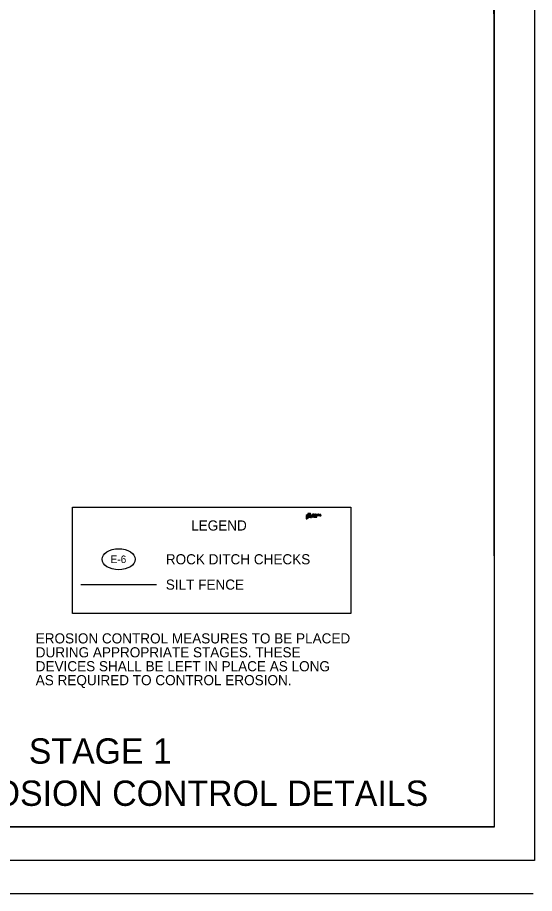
# Model space of a CAD drawing. Extents: x 7675 to 14104, y 9961 to 11168.
# Drawn here: x 11298 to 11605, y 9961 to 10480 of the extents above; entities that cross this region are included whole.
import ezdxf

# ---------------------------------------------------------------- set-up
doc = ezdxf.new("R2010")
doc.units = 0
for name, color, linetype in [('GREEN_TXT', 7, 'Continuous'), ('Legend', 7, 'Continuous'), ('S_TREE', 7, 'Continuous'), ('SEAL-INFO', 7, 'Continuous'), ('Stage 1 Ditch Checks', 7, 'Continuous')]:
    doc.layers.add(name, color=color, linetype=linetype)

msp = doc.modelspace()

# ---------------------------------------------------------------- linework, layer by layer
at = {"layer": 'GREEN_TXT'}
for p, q in [((11580.9, 10000), (11580.9, 11027.3)), ((11580.9, 10000), (10000, 10000)), ((9843.9, 9960.6), (11603.9, 9960.6))]:
    msp.add_line(p, q, dxfattribs=at)
at = {"layer": 'Legend'}
for p, q in [((11469.47, 10183.1), (11470.88, 10183.92)), ((11469.48, 10183.63), (11470.68, 10184.33)), ((11469.48, 10182.58), (11471.09, 10183.5)), ((11470.76, 10185.41), (11471.69, 10185.41)), ((11471.71, 10185.39), (11471.81, 10184.8)), ((11473.03, 10184.29), (11473.03, 10184.3)), ((11473.03, 10183.49), (11473.03, 10183.49)), ((11473.04, 10185.3), (11473.04, 10185.3)), ((11473.04, 10184.49), (11473.04, 10184.49)), ((11473.04, 10183.51), (11473.04, 10183.51)), ((11473.06, 10184.51), (11473.05, 10184.51)), ((11473.05, 10183.46), (11473.23, 10183.46)), ((11473.06, 10184.47), (11473.24, 10184.47)), ((11473.06, 10184.25), (11473.06, 10183.53)), ((11473.07, 10185.26), (11473.07, 10184.54)), ((11473.22, 10183.97), (11473.22, 10184.19)), ((11473.22, 10183.53), (11473.22, 10183.85)), ((11473.23, 10184.92), (11473.23, 10185.21)), ((11473.24, 10184.54), (11473.24, 10184.77)), ((11473.24, 10184.21), (11473.64, 10184.21)), ((11473.52, 10183.95), (11473.24, 10183.95)), ((11473.24, 10183.5), (11473.24, 10183.51)), ((11473.25, 10184.8), (11473.5, 10184.87)), ((11473.25, 10184.51), (11473.25, 10184.51)), ((11473.25, 10183.87), (11473.52, 10183.87)), ((11473.25, 10183.49), (11473.25, 10183.49)), ((11473.26, 10185.24), (11473.34, 10185.24)), ((11473.39, 10184.96), (11473.27, 10184.9)), ((11473.27, 10184.49), (11473.27, 10184.49)), ((11473.56, 10183.84), (11473.56, 10183.83)), ((11473.68, 10184.18), (11473.68, 10184.16)), ((11473.8, 10184.49), (11473.8, 10184.49)), ((11473.81, 10184.01), (11473.82, 10184.01)), ((11473.81, 10183.47), (11474.02, 10183.47)), ((11473.82, 10184.47), (11474.03, 10184.47)), ((11473.97, 10184.05), (11473.82, 10184.05)), ((11473.98, 10185.06), (11473.83, 10185.06)), ((11473.83, 10185.02), (11473.83, 10185.01)), ((11473.83, 10183.99), (11473.83, 10183.53)), ((11473.85, 10184.99), (11473.85, 10184.54)), ((11473.99, 10183.54), (11473.99, 10184.03)), ((11474.01, 10184.54), (11474.01, 10185.04)), ((11474.02, 10183.51), (11474.02, 10183.51)), ((11474.03, 10184.51), (11474.03, 10184.52)), ((11474.19, 10183.46), (11474.4, 10183.46)), ((11474.35, 10184.05), (11474.2, 10184.05)), ((11474.2, 10184.01), (11474.2, 10184.01)), ((11474.21, 10183.99), (11474.21, 10183.53)), ((11474.37, 10183.53), (11474.37, 10183.86)), ((11474.4, 10183.51), (11474.4, 10183.51)), ((11474.57, 10184.9), (11474.64, 10184.98)), ((11474.72, 10184.47), (11474.92, 10184.47)), ((11474.72, 10184.01), (11474.72, 10184.01)), ((11474.87, 10185.32), (11474.73, 10185.32)), ((11474.73, 10185.28), (11474.73, 10185.28)), ((11474.73, 10183.99), (11474.73, 10183.53)), ((11474.74, 10185.26), (11474.74, 10184.53)), ((11474.9, 10184.86), (11474.9, 10185.3)), ((11474.9, 10184.69), (11474.97, 10184.75)), ((11474.9, 10184.53), (11474.9, 10184.67)), ((11474.9, 10183.54), (11474.9, 10183.86)), ((11474.92, 10183.51), (11474.92, 10183.51)), ((11475.08, 10184.97), (11474.94, 10184.84)), ((11475.01, 10184.74), (11475.13, 10184.53)), ((11475.08, 10185.04), (11475.09, 10185)), ((11475.31, 10185.07), (11475.1, 10185.07)), ((11475.1, 10183.51), (11475.1, 10183.51)), ((11475.12, 10184.47), (11475.37, 10184.47)), ((11475.12, 10183.86), (11475.12, 10183.54)), ((11475.14, 10184.9), (11475.29, 10185.03)), ((11475.34, 10184.52), (11475.14, 10184.87)), ((11475.28, 10183.54), (11475.28, 10183.87)), ((11475.31, 10185.03), (11475.32, 10185.03)), ((11475.31, 10183.51), (11475.31, 10183.51)), ((11475.33, 10185.04), (11475.33, 10185.05)), ((11475.51, 10184.9), (11475.51, 10184.9)), ((11475.51, 10183.87), (11475.51, 10183.53)), ((11475.52, 10184.82), (11475.87, 10184.82)), ((11475.72, 10184.87), (11475.53, 10184.87)), ((11475.67, 10183.54), (11475.67, 10183.87)), ((11475.7, 10183.51), (11475.69, 10183.51)), ((11475.87, 10184.62), (11475.87, 10184.62)), ((11475.97, 10184.47), (11476.19, 10184.47)), ((11475.98, 10185.02), (11475.98, 10185.01)), ((11476.14, 10185.06), (11475.99, 10185.06)), ((11476, 10184.99), (11476, 10184.54)), ((11476.16, 10184.54), (11476.16, 10184.87)), ((11476.19, 10184.51), (11476.18, 10184.52)), ((11476.44, 10184.47), (11476.65, 10184.47)), ((11476.45, 10185.02), (11476.45, 10185.01)), ((11476.6, 10185.06), (11476.46, 10185.06)), ((11476.47, 10184.99), (11476.47, 10184.54)), ((11476.63, 10184.54), (11476.63, 10185.03)), ((11476.65, 10184.51), (11476.65, 10184.52)), ((11476.76, 10184.47), (11476.97, 10184.47)), ((11476.77, 10185.02), (11476.77, 10185.01)), ((11476.92, 10185.06), (11476.78, 10185.06)), ((11476.79, 10184.99), (11476.79, 10184.54)), ((11476.95, 10184.54), (11476.95, 10184.87)), ((11476.97, 10184.51), (11476.97, 10184.52)), ((11477.15, 10184.47), (11477.36, 10184.47)), ((11477.17, 10184.87), (11477.17, 10184.54)), ((11477.33, 10184.54), (11477.33, 10184.87)), ((11477.36, 10184.51), (11477.36, 10184.52)), ((11478.03, 10185.06), (11477.8, 10185.06)), ((11477.86, 10184.94), (11477.86, 10184.65)), ((11477.88, 10184.46), (11477.88, 10184.46)), ((11478, 10184.63), (11478, 10184.98)), ((11478.01, 10185), (11478.05, 10185.02)), ((11335.77, 10143.59), (11380.77, 10143.59))]:
    msp.add_line(p, q, dxfattribs=at)
msp.add_lwpolyline([(11330.89, 10189.39), (11495.89, 10189.39), (11495.89, 10126.39), (11330.89, 10126.39)], close=True, dxfattribs=at)
for points in [[(11472.14, 10185.07), (11472.02, 10185.76), (11472, 10185.78), (11470.43, 10185.78), (11470.4, 10185.76), (11470.28, 10185.05), (11469.44, 10184.57), (11469.43, 10184.54), (11469.43, 10184.17), (11469.47, 10184.15)], [(11470.51, 10184.66), (11469.45, 10184.04), (11469.44, 10184.02), (11469.44, 10183.65), (11469.48, 10183.63)], [(11470.71, 10184.26), (11469.45, 10183.52), (11469.44, 10183.5), (11469.44, 10183.12), (11469.47, 10183.1)], [(11470.91, 10183.86), (11469.45, 10182.99), (11469.44, 10182.97), (11469.44, 10182.6), (11469.48, 10182.58)], [(11469.47, 10184.15), (11470.61, 10184.78), (11470.62, 10184.8), (11470.73, 10185.39)], [(11472.53, 10184.59), (11472.55, 10184.61), (11472.55, 10184.93), (11472.53, 10184.96)], [(11472.53, 10184.14), (11472.55, 10184.17), (11472.55, 10184.49), (11472.53, 10184.51)], [(11472.53, 10183.69), (11472.55, 10183.71), (11472.55, 10184.04), (11472.53, 10184.06)], [(11472.53, 10183.23), (11472.55, 10183.25), (11472.55, 10183.59), (11472.53, 10183.62)], [(11473.68, 10184.32), (11473.05, 10184.32), (11473.05, 10184.32)], [(11473.43, 10185.33), (11473.06, 10185.33), (11473.06, 10185.32)], [(11473.57, 10184.01), (11473.58, 10184.01), (11473.57, 10184.01), (11473.56, 10184), (11473.56, 10183.98)], [(11473.57, 10183.82), (11473.58, 10183.82), (11473.57, 10183.82)], [(11473.58, 10183.83), (11473.59, 10183.83), (11473.59, 10184), (11473.58, 10184)], [(11473.7, 10184.16), (11473.71, 10184.16), (11473.71, 10184.3)], [(11473.79, 10183.49), (11473.79, 10183.49), (11473.79, 10183.49)], [(11473.8, 10184.03), (11473.8, 10184.03), (11473.8, 10184.03)], [(11473.81, 10185.04), (11473.81, 10185.04), (11473.81, 10185.04)], [(11473.81, 10183.51), (11473.81, 10183.51), (11473.81, 10183.51)], [(11473.82, 10184.52), (11473.82, 10184.52), (11473.82, 10184.51)], [(11474.04, 10183.49), (11474.04, 10183.49), (11474.04, 10183.49)], [(11474.05, 10184.49), (11474.05, 10184.49), (11474.05, 10184.49)], [(11474.17, 10183.49), (11474.17, 10183.49), (11474.17, 10183.49)], [(11474.18, 10184.03), (11474.18, 10184.03), (11474.18, 10184.03)], [(11474.19, 10183.51), (11474.19, 10183.51), (11474.19, 10183.51)], [(11474.42, 10183.49), (11474.42, 10183.49), (11474.42, 10183.49)], [(11474.55, 10183.98), (11474.59, 10183.95), (11474.6, 10183.96), (11474.6, 10184.08), (11474.59, 10184.1), (11474.54, 10184.1)], [(11474.58, 10184.48), (11474.62, 10184.47), (11474.63, 10184.48), (11474.63, 10184.61)], [(11474.69, 10183.49), (11474.71, 10183.47), (11474.92, 10183.47), (11474.94, 10183.49)], [(11474.89, 10184.04), (11474.87, 10184.05), (11474.72, 10184.05), (11474.7, 10184.03)], [(11474.71, 10183.51), (11474.71, 10183.51), (11474.71, 10183.51)], [(11474.72, 10184.52), (11474.72, 10184.52), (11474.72, 10184.51)], [(11474.92, 10184.51), (11474.92, 10184.52), (11474.92, 10184.52)], [(11475.07, 10183.49), (11475.1, 10183.47), (11475.31, 10183.47), (11475.33, 10183.49)], [(11475.12, 10184.52), (11475.12, 10184.52), (11475.12, 10184.51)], [(11475.37, 10184.51), (11475.37, 10184.52), (11475.36, 10184.52)], [(11475.46, 10183.49), (11475.48, 10183.47), (11475.7, 10183.47), (11475.72, 10183.49)], [(11475.49, 10183.51), (11475.49, 10183.51), (11475.48, 10183.51)], [(11475.84, 10184.48), (11475.88, 10184.47), (11475.89, 10184.48), (11475.89, 10184.61)], [(11475.95, 10184.49), (11475.95, 10184.49), (11475.95, 10184.49)], [(11475.97, 10185.04), (11475.97, 10185.03), (11475.97, 10185.04)], [(11475.98, 10184.52), (11475.98, 10184.52), (11475.97, 10184.51)], [(11476.21, 10184.49), (11476.21, 10184.49), (11476.21, 10184.49)], [(11476.34, 10184.99), (11476.38, 10184.95), (11476.39, 10184.97), (11476.39, 10185.09), (11476.38, 10185.1), (11476.32, 10185.1)], [(11476.42, 10184.49), (11476.42, 10184.49), (11476.42, 10184.49)], [(11476.44, 10185.04), (11476.44, 10185.03), (11476.44, 10185.04)], [(11476.45, 10184.52), (11476.44, 10184.52), (11476.44, 10184.51)], [(11476.68, 10184.49), (11476.68, 10184.49), (11476.68, 10184.49)], [(11476.74, 10184.49), (11476.74, 10184.49), (11476.74, 10184.49)], [(11476.75, 10185.04), (11476.75, 10185.03), (11476.75, 10185.04)], [(11476.77, 10184.52), (11476.76, 10184.52), (11476.76, 10184.51)], [(11476.99, 10184.49), (11476.99, 10184.49), (11476.99, 10184.49)], [(11477.13, 10184.49), (11477.13, 10184.49), (11477.13, 10184.49)], [(11477.15, 10184.52), (11477.15, 10184.52), (11477.15, 10184.51)], [(11477.38, 10184.49), (11477.38, 10184.49), (11477.38, 10184.49)], [(11477.56, 10184.31), (11477.56, 10184.36), (11477.55, 10184.38), (11477.51, 10184.4), (11477.41, 10184.32)]]:
    msp.add_lwpolyline(points, dxfattribs=at)
for centre, radius, start, end in [((11471.23, 10183.21), 1.62, 63.44, 116.2443), ((11471.23, 10183.21), 1.24, 63.4399, 116.2445), ((11471.23, 10183.21), 1.16, 63.4396, 116.2455), ((11470.76, 10185.39), 0.0257, 90, 169.3947), ((11471.23, 10183.21), 0.79, 63.4406, 116.2427), ((11471.23, 10183.21), 0.717, 63.443, 116.2359), ((11471.23, 10183.21), 0.326, 63.4385, 116.2484), ((11472.55, 10185.86), 2.63, 243.4196, 269.4358), ((11472.55, 10185.86), 2.24, 243.4196, 269.3512), ((11472.55, 10185.86), 2.17, 243.4196, 269.3138), ((11471.69, 10185.39), 0.0257, 9.4561, 90), ((11472.55, 10185.86), 1.79, 243.4196, 269.1919), ((11472.55, 10185.86), 1.72, 243.4196, 269.1297), ((11471.23, 10183.21), 1.69, 63.4196, 69.8726), ((11472.55, 10185.86), 1.34, 243.4196, 268.9264), ((11472.55, 10185.86), 1.27, 243.4196, 268.8202), ((11472.17, 10185.07), 0.0257, 189.9771, 243.8715), ((11472.55, 10185.86), 0.9, 243.8715, 268.4109), ((11473.05, 10184.3), 0.0212, 82.6236, 189.0072), ((11473.05, 10184.3), 0.0212, 181.5218, 256.2604), ((11473.05, 10183.48), 0.021, 103.7396, 178.4782), ((11473.05, 10183.48), 0.021, 170.9928, 274.1452), ((11473.06, 10185.3), 0.0212, 82.6236, 189.0072), ((11473.06, 10185.3), 0.0212, 181.5218, 256.2604), ((11473.06, 10184.49), 0.021, 103.7396, 178.4782), ((11473.06, 10184.49), 0.021, 170.9928, 274.1452), ((11473.03, 10184.25), 0.0259, 358.7571, 66.0872), ((11473.03, 10183.53), 0.0259, 293.9128, 6.4972), ((11473.04, 10185.26), 0.0259, 358.7571, 66.0872), ((11473.04, 10184.54), 0.0259, 293.9128, 6.4972), ((11473.24, 10184.19), 0.0234, 90, 180), ((11473.24, 10183.97), 0.0234, 180, 270), ((11473.25, 10183.85), 0.0234, 90, 180), ((11473.25, 10183.53), 0.0259, 174.5041, 246.0872), ((11473.26, 10185.21), 0.0234, 90, 180), ((11473.26, 10184.92), 0.0234, 180, 295.644), ((11473.23, 10183.48), 0.021, 260.4108, 9.0072), ((11473.26, 10184.77), 0.0234, 115.5876, 180), ((11473.26, 10184.54), 0.0259, 174.5041, 246.0872), ((11473.25, 10184.49), 0.021, 260.4108, 9.0071), ((11473.23, 10183.48), 0.021, 1.5218, 76.2604), ((11473.25, 10184.49), 0.021, 1.5218, 76.2604), ((11473.37, 10185.07), 0.163, 26.6835, 99.2796), ((11473.1, 10185.44), 0.563, 300.9494, 314.2537), ((11473.47, 10184.87), 0.455, 79.5817, 94.0737), ((11473.44, 10185.11), 0.0889, 308.8414, 26.6835), ((11473.25, 10185.45), 0.631, 293.1872, 299.0408), ((11473.52, 10183.98), 0.0351, 270, 0), ((11473.52, 10183.84), 0.0351, 0, 90), ((11473.51, 10185.12), 0.205, 346.8336, 79.1626), ((11473.47, 10185.13), 0.242, 290.3558, 346.8336), ((11473.57, 10183.83), 0.0117, 180, 270), ((11473.57, 10184), 0.0117, 0, 90), ((11473.57, 10183.83), 0.0117, 270, 0), ((11473.64, 10184.18), 0.0351, 360, 90), ((11473.68, 10184.3), 0.0234, 360, 90), ((11473.69, 10184.16), 0.0117, 180, 270), ((11473.69, 10184.16), 0.0117, 270, 0), ((11473.81, 10183.49), 0.0211, 90, 180), ((11473.81, 10183.49), 0.0211, 180, 270), ((11473.82, 10184.49), 0.0211, 90, 179.9884), ((11473.82, 10184.49), 0.0211, 180, 270), ((11473.82, 10184.03), 0.0211, 90, 180), ((11473.82, 10184.03), 0.0211, 180, 250.953), ((11473.83, 10185.04), 0.0211, 90, 180), ((11473.83, 10185.04), 0.0211, 180, 250.953), ((11473.81, 10183.53), 0.0211, 270, 360), ((11473.82, 10184.54), 0.0211, 270, 360), ((11473.81, 10183.99), 0.0234, 0, 70.953), ((11473.82, 10184.99), 0.0234, 0, 70.953), ((11473.93, 10185.23), 0.0853, 0, 180), ((11473.93, 10185.23), 0.0853, 180, 0), ((11473.97, 10184.03), 0.0234, 0, 90), ((11473.98, 10185.04), 0.0234, 0, 90), ((11474.02, 10183.54), 0.0234, 180, 270), ((11474.03, 10184.54), 0.0234, 180, 270), ((11474.02, 10183.49), 0.0211, 360, 90), ((11474.02, 10183.49), 0.0211, 270, 0), ((11474.03, 10184.49), 0.0211, 0, 90), ((11474.03, 10184.49), 0.0211, 270, 0), ((11474.43, 10184.8), 0.335, 159.4493, 258.0401), ((11474.35, 10184.86), 0.236, 89.5501, 165.3049), ((11474.19, 10183.49), 0.0211, 90, 180), ((11474.19, 10183.49), 0.0211, 180, 270), ((11474.2, 10184.03), 0.0211, 90, 180), ((11474.2, 10184.03), 0.0211, 180, 250.953), ((11474.19, 10183.53), 0.0211, 270, 0), ((11474.19, 10183.99), 0.0234, 360, 70.953), ((11474.6, 10184.8), 0.336, 157.5816, 204.7596), ((11474.43, 10184.84), 0.166, 85.3224, 146.7414), ((11474.49, 10184.8), 0.242, 216.7971, 248.1851), ((11474.34, 10184.62), 0.476, 51.4978, 89.5501), ((11474.35, 10184.03), 0.0234, 31.1414, 90), ((11474.45, 10184.87), 0.404, 257.1029, 287.6234), ((11474.38, 10184.05), 0.0117, 211.1414, 301.6677), ((11474.52, 10183.85), 0.142, 82.1433, 175.2273), ((11474.4, 10183.53), 0.0234, 180, 270), ((11474.62, 10183.66), 0.44, 100.4967, 121.6677), ((11474.47, 10184.79), 0.222, 251.3493, 311.1706), ((11474.4, 10183.49), 0.0211, 360, 90), ((11474.4, 10183.49), 0.0211, 270, 0), ((11474.42, 10184.8), 0.199, 60.5413, 85.3224), ((11474.49, 10184.92), 0.0688, 353.0776, 57.5568), ((11474.53, 10183.97), 0.0234, 33.0334, 82.1433), ((11474.57, 10184.91), 0.0117, 173.0776, 318.3482), ((11474.58, 10184.47), 0.0117, 72.7237, 107.6234), ((11474.62, 10184.61), 0.0117, 0, 131.1706), ((11474.63, 10184.98), 0.0117, 318.3482, 51.4978), ((11474.71, 10183.49), 0.0211, 90, 173.9744), ((11474.72, 10184.49), 0.0211, 90, 180), ((11474.72, 10184.49), 0.0211, 180, 270), ((11474.72, 10184.03), 0.0211, 185.1813, 250.953), ((11474.73, 10185.3), 0.0211, 90, 180), ((11474.73, 10185.3), 0.0211, 180, 250.953), ((11474.71, 10183.53), 0.0211, 270, 0), ((11474.72, 10184.53), 0.0187, 270, 360), ((11474.71, 10183.99), 0.0234, 360, 70.953), ((11474.72, 10185.26), 0.0234, 360, 70.953), ((11474.87, 10185.3), 0.0234, 360, 90), ((11474.9, 10184.05), 0.0117, 211.1414, 301.6677), ((11475.01, 10183.87), 0.114, 354.6239, 185.3761), ((11474.92, 10184.86), 0.0234, 180, 311.0699), ((11474.92, 10184.67), 0.0234, 131.0699, 180), ((11474.92, 10184.53), 0.0187, 180, 270), ((11474.92, 10183.54), 0.0234, 180, 270), ((11475.06, 10183.88), 0.221, 38.0335, 134.0608), ((11474.92, 10184.49), 0.0211, 0, 90), ((11474.92, 10184.49), 0.0211, 270, 0), ((11474.92, 10183.49), 0.0211, 6.0256, 90), ((11474.99, 10184.73), 0.0234, 31.2702, 131.0699), ((11475.1, 10183.49), 0.0211, 90, 173.9744), ((11475.1, 10185.05), 0.0234, 90, 199.4367), ((11475.07, 10184.99), 0.0234, 311.0699, 19.4367), ((11475.12, 10184.49), 0.0211, 90, 180), ((11475.12, 10184.49), 0.0211, 180, 270), ((11475.1, 10183.54), 0.0234, 270, 0), ((11475.12, 10184.53), 0.0117, 270, 31.2702), ((11475.16, 10184.88), 0.0234, 131.0699, 211.2702), ((11475.25, 10184.03), 0.0234, 218.0335, 322.8576), ((11475.45, 10183.88), 0.221, 355.8732, 142.8576), ((11475.4, 10183.88), 0.114, 354.6239, 185.3761), ((11475.31, 10183.54), 0.0234, 180, 270), ((11475.31, 10185.01), 0.0234, 90, 131.0699), ((11475.31, 10185.05), 0.0234, 0, 90), ((11475.31, 10183.49), 0.0211, 6.0256, 90), ((11475.32, 10185.04), 0.0117, 270, 0), ((11475.66, 10184.8), 0.335, 159.4493, 258.0401), ((11475.36, 10184.53), 0.0187, 211.2702, 270), ((11475.57, 10184.86), 0.236, 89.5501, 165.3049), ((11475.37, 10184.49), 0.0211, 0, 90), ((11475.37, 10184.49), 0.0211, 270, 0), ((11475.48, 10183.49), 0.0211, 90, 173.9744), ((11475.52, 10184.79), 0.0234, 90, 181.0387), ((11475.83, 10184.8), 0.336, 181.0387, 204.7596), ((11475.49, 10183.53), 0.0211, 270, 0), ((11475.83, 10184.8), 0.336, 157.5816, 162.6114), ((11475.53, 10184.89), 0.0234, 162.6114, 270), ((11475.63, 10184.89), 0.117, 0.3238, 162.4345), ((11475.72, 10184.8), 0.242, 216.7971, 248.1851), ((11475.57, 10184.62), 0.476, 70.5239, 89.5501), ((11475.69, 10184.99), 0.52, 258.6424, 285.5129), ((11475.71, 10184.85), 0.279, 253.3482, 306.5566), ((11475.69, 10183.54), 0.0234, 180, 270), ((11475.7, 10183.49), 0.0211, 6.0256, 90), ((11475.72, 10184.89), 0.0234, 270, 0.3238), ((11475.67, 10184.85), 0.226, 357.7955, 73.16), ((11475.84, 10184.47), 0.0117, 72.7237, 107.6234), ((11475.87, 10184.84), 0.0234, 270, 11.363), ((11475.88, 10184.61), 0.0117, 360, 131.1706), ((11475.97, 10184.49), 0.0211, 90, 180), ((11475.97, 10184.49), 0.0211, 180, 270), ((11475.99, 10185.04), 0.0211, 90, 180), ((11475.99, 10185.04), 0.0211, 180, 250.953), ((11475.98, 10184.99), 0.0234, 0, 70.953), ((11475.98, 10184.54), 0.0211, 270, 0), ((11476.14, 10185.03), 0.0234, 31.1414, 90), ((11476.17, 10185.05), 0.0117, 211.1414, 301.6677), ((11476.3, 10184.86), 0.142, 82.1433, 175.2273), ((11476.18, 10184.54), 0.0234, 180, 270), ((11476.4, 10184.67), 0.44, 100.4967, 121.6677), ((11476.19, 10184.49), 0.0211, 0, 90), ((11476.19, 10184.49), 0.0211, 270, 360), ((11476.32, 10184.97), 0.0234, 33.0334, 82.1433), ((11476.44, 10184.49), 0.0211, 90, 180), ((11476.44, 10184.49), 0.0211, 180, 270), ((11476.46, 10185.04), 0.0211, 90, 180), ((11476.46, 10185.04), 0.0211, 180, 250.953), ((11476.44, 10184.99), 0.0234, 0, 70.953), ((11476.45, 10184.54), 0.0211, 270, 0), ((11476.54, 10185.23), 0.0853, 0, 180), ((11476.54, 10185.23), 0.0853, 180, 0), ((11476.6, 10185.03), 0.0234, 0, 90), ((11476.65, 10184.54), 0.0234, 180, 270), ((11476.65, 10184.49), 0.0211, 0, 90), ((11476.65, 10184.49), 0.0211, 270, 0), ((11476.76, 10184.49), 0.0211, 90, 180), ((11476.76, 10184.49), 0.0211, 180, 270), ((11476.78, 10185.04), 0.0211, 90, 180), ((11476.78, 10185.04), 0.0211, 180, 250.953), ((11476.76, 10184.99), 0.0234, 0, 70.953), ((11476.77, 10184.54), 0.0211, 270, 0), ((11476.92, 10185.03), 0.0234, 31.1414, 90), ((11476.95, 10185.05), 0.0117, 211.1414, 301.6677), ((11477.06, 10184.88), 0.114, 354.6239, 185.3761), ((11476.97, 10184.54), 0.0234, 180, 270), ((11477.11, 10184.88), 0.221, 355.8732, 134.0608), ((11476.97, 10184.49), 0.0211, 0, 90), ((11476.97, 10184.49), 0.0211, 270, 0), ((11477.15, 10184.49), 0.0211, 90, 180), ((11477.15, 10184.49), 0.0211, 180, 270), ((11477.15, 10184.54), 0.0211, 270, 0), ((11477.36, 10184.54), 0.0234, 180, 270), ((11477.36, 10184.49), 0.0211, 0, 90), ((11477.36, 10184.49), 0.0211, 270, 0), ((11477.43, 10184.3), 0.0234, 131.168, 231.4342), ((11477.73, 10184.69), 0.516, 231.4342, 293.5615), ((11477.75, 10184.73), 0.334, 82.2082, 193.6815), ((11477.65, 10184.71), 0.236, 194.6951, 270.4499), ((11477.59, 10184.31), 0.0234, 180, 236.707), ((11477.69, 10184.47), 0.211, 236.707, 290.0983), ((11477.81, 10184.74), 0.225, 83.4753, 215.9717), ((11477.73, 10184.7), 0.138, 223.5865, 338.2119), ((11477.55, 10185.07), 0.606, 280.0346, 297.3499), ((11477.73, 10184.43), 0.158, 282.8124, 14.1312), ((11477.84, 10184.51), 0.0234, 13.323, 128.4784), ((11477.84, 10184.94), 0.0234, 0, 83.4753), ((11478.39, 10184.64), 0.539, 193.323, 199.0669), ((11478.39, 10184.64), 0.539, 199.0669, 199.752), ((11477.83, 10184.39), 0.213, 302.2961, 7.2223), ((11478.02, 10184.98), 0.0234, 135.4319, 180), ((11478.42, 10184.6), 0.419, 175.3173, 204.9345), ((11478.03, 10185.03), 0.0234, 315.4319, 90)]:
    msp.add_arc(centre, radius, start, end, dxfattribs=at)
msp.add_ellipse((11358.27, 10158.59), major_axis=(9.78, 0), ratio=0.638788, dxfattribs=at)
at = {"layer": 'SEAL-INFO'}
msp.add_lwpolyline([(9937.96, 11046.77), (11604.66, 11046.77), (11604.66, 9980.09), (9937.96, 9980.09)], close=True, dxfattribs=at)
at = {"layer": 'Stage 1 Ditch Checks'}
msp.add_lwpolyline([(10000, 10000), (11580.9, 10000), (11580.3, 10963.3), (11365.4, 10963.3), (11357.31, 10959.87), (11348.49, 10961.4), (11348.26, 10977.9), (11169.6, 10977.9), (11169.6, 11027.3), (10000, 11027.3)], close=True, dxfattribs=at)

# ---------------------------------------------------------------- texts
at = {"layer": 'GREEN_TXT'}
for s, p in [('STAGE 1', (11305.03, 10037.5)), ('TEMPORARY EROSION CONTROL DETAILS', (11123.73, 10012.5))]:
    msp.add_text(s, height=15, dxfattribs=at).set_placement(p)
at = {"layer": 'Legend'}
for s, height, p in [('LEGEND', 6, (11401.21, 10175.59)), ('E-6', 4.464, (11353.49, 10156.36)), ('ROCK DITCH CHECKS', 6, (11386.21, 10155.59)), ('SILT FENCE', 6, (11386.21, 10140.59))]:
    msp.add_text(s, height=height, dxfattribs=at).set_placement(p)
at = {"layer": 'S_TREE'}
for s, p in [('EROSION CONTROL MEASURES TO BE PLACED ', (11309.12, 10108.72)), ('DURING APPROPRIATE STAGES. THESE ', (11309.12, 10100.47)), ('DEVICES SHALL BE LEFT IN PLACE AS LONG ', (11309.12, 10092.22)), ('AS REQUIRED TO CONTROL EROSION.', (11309.12, 10083.97))]:
    msp.add_text(s, height=6, dxfattribs=at).set_placement(p)

doc.saveas('drawing.dxf')
